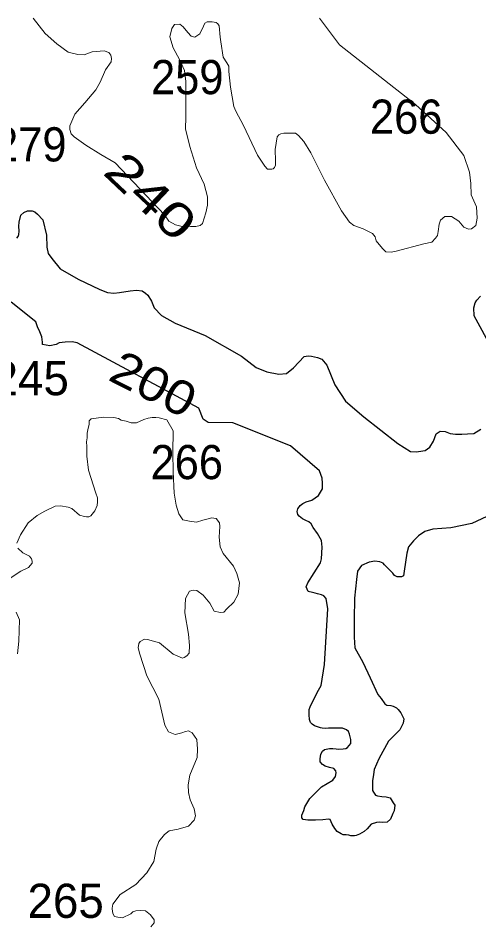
# Model space of a CAD drawing. Extents: x 445.4 to 500, y 8728.7 to 8784.
# Drawn here: x 479.664 to 481.821, y 8779.753 to 8784.001 of the extents above; entities that cross this region are included whole.
import ezdxf
from ezdxf.enums import TextEntityAlignment as Align

# ---------------------------------------------------------------- set-up
doc = ezdxf.new("R2010")
doc.units = 0
doc.header["$LTSCALE"] = 0.064
doc.layers.add('1', color=7, linetype='Continuous', lineweight=25)
doc.layers.add('2', color=7, linetype='Continuous', lineweight=13)
doc.layers.add('21', color=7, linetype='Continuous')
doc.layers.add('61', color=7, linetype='Continuous')

msp = doc.modelspace()

# ---------------------------------------------------------------- linework, layer by layer
at = {"layer": '1'}
for points in [[(479.6569, 8782.9699), (479.6644, 8782.9774), (479.6674, 8782.988), (479.6682, 8783.0038), (479.6674, 8783.0272), (479.6682, 8783.0453), (479.6759, 8783.0788), (479.6902, 8783.0902), (479.7068, 8783.0977), (479.7287, 8783.0977), (479.7415, 8783.0932), (479.7551, 8783.0834), (479.78, 8783.0562), (479.7966, 8782.9846), (479.7982, 8782.9283), (479.805, 8782.8989), (479.8216, 8782.8748), (479.8601, 8782.8265), (479.9446, 8782.779), (480.0459, 8782.7303), (480.0824, 8782.7162), (480.1118, 8782.712), (480.1385, 8782.7162), (480.1876, 8782.7232), (480.2171, 8782.726), (480.2438, 8782.7232), (480.2592, 8782.7134), (480.2704, 8782.7036), (480.2887, 8782.6756), (480.3013, 8782.6433), (480.3346, 8782.6087), (480.3992, 8782.5723), (480.5396, 8782.5148), (480.7094, 8782.4181), (480.7782, 8782.3648), (480.8273, 8782.3438), (480.8273, 8782.3438), (480.8849, 8782.3325), (480.8849, 8782.3325), (480.9199, 8782.3368), (480.9522, 8782.3634), (481.0028, 8782.4153), (481.021, 8782.4195), (481.0364, 8782.4167), (481.0659, 8782.4111), (481.085, 8782.4032), (481.1089, 8782.3752), (481.1468, 8782.2827), (481.1959, 8782.207)], [(481.8837, 8782.4485), (481.798, 8782.6069), (481.7977, 8782.6445), (481.8033, 8782.667), (481.8118, 8782.6796), (481.8286, 8782.6992)], [(481.0809, 8780.5527), (481.0892, 8780.5669), (481.0986, 8780.574), (481.1211, 8780.5787), (481.1364, 8780.5787), (481.1518, 8780.5775), (481.1647, 8780.5763), (481.1848, 8780.5775), (481.1978, 8780.5798), (481.2061, 8780.5846), (481.2061, 8780.5846), (481.2214, 8780.6023), (481.2214, 8780.6211), (481.2144, 8780.6469), (481.2097, 8780.6587), (481.2014, 8780.6669), (481.1826, 8780.6752), (481.1613, 8780.674), (481.1306, 8780.674), (481.1164, 8780.674), (481.1023, 8780.6728), (481.0869, 8780.6752), (481.0798, 8780.6764), (481.0656, 8780.6811), (481.0515, 8780.6858), (481.0408, 8780.6929), (481.0326, 8780.7011), (481.0279, 8780.7153), (481.0267, 8780.7365), (481.0267, 8780.7613), (481.0302, 8780.7743), (481.0633, 8780.8415), (481.0822, 8780.8745), (481.0987, 8780.9736), (481.1129, 8781.234), (481.1058, 8781.2823), (481.0952, 8781.2941), (481.0846, 8781.3), (481.0657, 8781.3047), (481.0539, 8781.3071), (481.0421, 8781.3106), (481.0208, 8781.3142), (481.0208, 8781.3142), (481.0125, 8781.3366), (481.0196, 8781.3553), (481.0799, 8781.4485), (481.0834, 8781.4685), (481.0869, 8781.5228), (481.0834, 8781.5534), (481.0645, 8781.5865), (481.0456, 8781.6148), (481.0362, 8781.6313), (481.0244, 8781.6419), (481.0102, 8781.6478), (480.9948, 8781.656), (480.9866, 8781.6619), (480.9795, 8781.6678), (480.9724, 8781.6761), (480.97, 8781.6891), (480.9724, 8781.702), (480.9842, 8781.7174), (480.9972, 8781.7268), (481.0125, 8781.7351), (481.0385, 8781.7422), (481.0705, 8781.7642), (481.0882, 8781.7961), (481.0882, 8781.822), (481.087, 8781.8456), (481.0743, 8781.8806), (480.939, 8781.9968), (480.6685, 8782.1044), (480.5529, 8782.107), (480.5299, 8782.122), (480.5099, 8782.1739), (479.9406, 8782.4806), (479.9173, 8782.4848), (479.8834, 8782.4827), (479.8559, 8782.4806), (479.841, 8782.4721), (479.841, 8782.4721), (479.8114, 8782.4658), (479.7775, 8782.4721), (479.7775, 8782.4827), (479.7754, 8782.5081), (479.7648, 8782.5314), (479.7542, 8782.5546), (479.7458, 8782.5779), (479.6314, 8782.6709)], [(481.1959, 8782.207), (481.2815, 8782.1326), (481.4415, 8782.0079), (481.5005, 8781.9714), (481.5286, 8781.97), (481.558, 8781.9742), (481.5693, 8781.9756), (481.5917, 8781.991), (481.6086, 8782.0191), (481.6208, 8782.0536), (481.6208, 8782.0536), (481.6391, 8782.0662), (481.6629, 8782.0648), (481.6868, 8782.055), (481.7107, 8782.0522), (481.7415, 8782.0522), (481.7668, 8782.0536), (481.7963, 8782.055), (481.83, 8782.076)], [(481.8576, 8781.6656), (481.7879, 8781.6337), (481.6887, 8781.6125)], [(481.6887, 8781.6125), (481.6049, 8781.6066), (481.5671, 8781.596), (481.5376, 8781.5759), (481.5139, 8781.5523), (481.4915, 8781.524), (481.4832, 8781.4945), (481.4703, 8781.4096), (481.4679, 8781.3884), (481.4584, 8781.3837), (481.4384, 8781.3837), (481.4254, 8781.3896), (481.4171, 8781.4014), (481.4006, 8781.4179), (481.3781, 8781.4403), (481.3722, 8781.4474), (481.3569, 8781.4533), (481.3336, 8781.4565), (481.3064, 8781.4529), (481.271, 8781.4364), (481.2521, 8781.4105), (481.2474, 8781.3704), (481.2391, 8781.2831), (481.237, 8781.1844), (481.237, 8781.1006), (481.2406, 8781.0511), (481.2772, 8780.9838), (481.3114, 8780.9107), (481.3472, 8780.8331), (481.3625, 8780.813), (481.3802, 8780.7883), (481.3897, 8780.7824), (481.4086, 8780.7812), (481.4192, 8780.7776), (481.4345, 8780.7694), (481.4428, 8780.7623), (481.4558, 8780.7458), (481.4688, 8780.7187), (481.4664, 8780.6986), (481.4511, 8780.6668), (481.3979, 8780.6137), (481.3528, 8780.5315), (481.3304, 8780.4808), (481.3269, 8780.4572), (481.3221, 8780.4277), (481.3221, 8780.4029), (481.3233, 8780.3829), (481.3269, 8780.3746), (481.3363, 8780.3605), (481.3457, 8780.3569), (481.3658, 8780.3546), (481.3859, 8780.3522), (481.4048, 8780.3475), (481.4201, 8780.3251), (481.4272, 8780.3145), (481.4237, 8780.2873), (481.4178, 8780.2755), (481.4072, 8780.2484), (481.3906, 8780.2343), (481.3906, 8780.2343), (481.3694, 8780.2331), (481.3564, 8780.2343), (481.341, 8780.2331), (481.3171, 8780.2252), (481.2971, 8780.2028), (481.2841, 8780.191), (481.2616, 8780.178), (481.2463, 8780.1721), (481.238, 8780.1709), (481.2215, 8780.1709), (481.212, 8780.1733), (481.199, 8780.1744), (481.1861, 8780.1756), (481.1766, 8780.1792), (481.1577, 8780.191), (481.1459, 8780.2051), (481.1341, 8780.2252), (481.1247, 8780.2464), (481.1164, 8780.2488), (481.0904, 8780.2452), (481.0562, 8780.2429), (481.0266, 8780.2429), (481.0207, 8780.244), (480.9983, 8780.2464), (480.9912, 8780.2547), (480.9912, 8780.2676), (481.0007, 8780.2889), (481.0054, 8780.3066), (481.0289, 8780.3451), (481.0833, 8780.3994), (481.1364, 8780.4312), (481.1494, 8780.4489), (481.1529, 8780.4654), (481.1506, 8780.4749), (481.1423, 8780.4855), (481.1211, 8780.4902), (481.101, 8780.4961), (481.088, 8780.5044), (481.0774, 8780.5162), (481.0774, 8780.5303), (481.0809, 8780.5527)]]:
    msp.add_lwpolyline(points, dxfattribs=at)
at = {"layer": '2'}
for points in [[(481.0745, 8784.0012), (481.1681, 8783.8757), (481.5247, 8783.597), (481.6681, 8783.4654), (481.7495, 8783.357), (481.7767, 8783.2796), (481.7832, 8783.2269), (481.785, 8783.1731), (481.8093, 8783.1176), (481.8128, 8783.0638), (481.8058, 8783.0291), (481.7867, 8783.0135), (481.7728, 8783.0118), (481.7502, 8783.0222), (481.7276, 8783.0499), (481.6929, 8783.0725), (481.6616, 8783.0725), (481.6407, 8783.0551), (481.6355, 8783.036), (481.6303, 8783.0013), (481.6268, 8782.9823), (481.6182, 8782.9701), (481.6008, 8782.951), (481.5626, 8782.9441), (481.434, 8782.9094), (481.4096, 8782.9042), (481.3853, 8782.9059), (481.3697, 8782.9215), (481.3401, 8782.958), (481.3349, 8782.9771), (481.3228, 8782.9927), (481.2793, 8783.0135), (481.2359, 8783.0291), (481.215, 8783.0447), (481.1768, 8783.0985), (481.0986, 8783.2425), (481.0339, 8783.3701), (481.0009, 8783.4239), (480.9766, 8783.4516), (480.9627, 8783.462), (480.9071, 8783.462), (480.8932, 8783.4586), (480.8845, 8783.4551), (480.8758, 8783.4447), (480.8671, 8783.3857), (480.8689, 8783.3319), (480.8689, 8783.3128), (480.8637, 8783.3007), (480.8584, 8783.2955), (480.8515, 8783.2937), (480.8306, 8783.2937), (480.8185, 8783.3076), (480.7837, 8783.3597), (480.7194, 8783.4985), (480.6823, 8783.5651), (480.6736, 8783.5877), (480.658, 8783.6779), (480.6493, 8783.7508), (480.6493, 8783.7768), (480.6406, 8783.7924), (480.6232, 8783.8189), (480.612, 8783.8909), (480.6094, 8783.9122), (480.6041, 8783.9645)], [(480.4213, 8783.973), (480.3958, 8783.9719), (480.3833, 8783.953), (480.374, 8783.9143), (480.3899, 8783.8619), (480.4194, 8783.808), (480.4427, 8783.7553), (480.4488, 8783.7039), (480.4488, 8783.6328), (480.4488, 8783.5365), (480.4476, 8783.4826), (480.4672, 8783.4005), (480.4991, 8783.3001), (480.5348, 8783.2233), (480.5495, 8783.1633), (480.5507, 8783.1253), (480.5421, 8783.0885), (480.5262, 8783.0383), (480.5151, 8783.0298), (480.4955, 8783.0249), (480.471, 8783.0249), (480.4256, 8783.0273), (480.3998, 8783.0334), (480.3692, 8783.0494), (480.3495, 8783.08), (480.1177, 8783.3237), (480.051, 8783.3625), (479.9799, 8783.4066), (479.9259, 8783.4446), (479.9124, 8783.4593), (479.905, 8783.4789), (479.9063, 8783.496), (479.9296, 8783.5512), (479.9762, 8783.6051), (480.0277, 8783.6651), (480.0485, 8783.7018), (480.0733, 8783.7589), (480.0991, 8783.7957), (480.1015, 8783.8128), (480.0978, 8783.8275), (480.088, 8783.8398), (480.0672, 8783.8484), (480.0107, 8783.8435), (479.9727, 8783.8288), (479.9433, 8783.8312), (479.8979, 8783.841), (479.8448, 8783.8804), (479.7909, 8783.9294), (479.7334, 8784.0004)], [(480.4213, 8783.973), (480.4362, 8783.9598), (480.4581, 8783.9335), (480.4735, 8783.9171), (480.4916, 8783.9127), (480.5148, 8783.928), (480.5308, 8783.9632), (480.5383, 8783.9775), (480.5494, 8783.9834), (480.572, 8783.9843), (480.5909, 8783.9815), (480.5993, 8783.9739), (480.6041, 8783.9645)], [(479.9904, 8782.0719), (479.9958, 8782.0986), (479.997, 8782.1145), (480.0056, 8782.1243), (480.0634, 8782.1311), (480.1122, 8782.1301), (480.1338, 8782.1254), (480.1457, 8782.117), (480.1688, 8782.1124), (480.1928, 8782.1044), (480.2185, 8782.1054), (480.2355, 8782.1131), (480.2524, 8782.1208), (480.2725, 8782.127), (480.2909, 8782.1301), (480.3079, 8782.1301), (480.3079, 8782.1301), (480.3244, 8782.1279), (480.3598, 8782.1187), (480.3896, 8782.0669), (480.388, 8781.9654), (480.3896, 8781.8761), (480.3942, 8781.776), (480.4034, 8781.7191), (480.4158, 8781.6791), (480.4343, 8781.6513), (480.4659, 8781.6443), (480.4982, 8781.6396), (480.5291, 8781.6489), (480.5537, 8781.655), (480.5691, 8781.6596), (480.5907, 8781.6566), (480.6061, 8781.6366), (480.6077, 8781.6196), (480.6046, 8781.5688), (480.6092, 8781.5242), (480.6231, 8781.4934), (480.6724, 8781.4334), (480.6878, 8781.3995), (480.7001, 8781.3555), (480.6939, 8781.3017), (480.6739, 8781.2647), (480.64, 8781.2339), (480.6261, 8781.2185), (480.6107, 8781.217), (480.5814, 8781.2232), (480.5614, 8781.2601), (480.5306, 8781.297), (480.4998, 8781.3201), (480.4828, 8781.3217), (480.4659, 8781.3171), (480.4474, 8781.2817), (480.4443, 8781.2155), (480.4612, 8781.1154), (480.4659, 8781.0615), (480.4643, 8781.0261), (480.4643, 8781.0261), (480.4535, 8781.0138), (480.4412, 8781.0061), (480.4335, 8781.003), (480.3888, 8781.0215), (480.3256, 8781.0739), (480.2693, 8781.0901), (480.2554, 8781.0916), (480.2354, 8781.0808), (480.2293, 8781.0716), (480.2262, 8781.0516), (480.2339, 8781.0208), (480.2662, 8780.9192), (480.3217, 8780.8099), (480.351, 8780.6883), (480.3669, 8780.6578), (480.3669, 8780.6578), (480.3993, 8780.6455), (480.4116, 8780.6486), (480.4301, 8780.6532), (480.4471, 8780.6594), (480.4471, 8780.6594), (480.4609, 8780.6624), (480.4779, 8780.6532), (480.4995, 8780.6209), (480.5041, 8780.5762), (480.5025, 8780.5378), (480.4671, 8780.4546), (480.4594, 8780.4085), (480.4609, 8780.3731), (480.4686, 8780.3392), (480.4871, 8780.2961), (480.4933, 8780.2638), (480.4871, 8780.2438), (480.4609, 8780.2161), (480.4126, 8780.2009), (480.371, 8780.1932), (480.3494, 8780.1763), (480.3217, 8780.144), (480.3093, 8780.107), (480.2985, 8780.0501), (480.2662, 8779.9962), (480.2153, 8779.9423), (480.1414, 8779.8946), (480.1075, 8779.85)], [(479.6578, 8781.5419), (479.6749, 8781.5798), (479.7104, 8781.636), (479.7532, 8781.6702), (479.7887, 8781.691), (479.8376, 8781.7142), (479.862, 8781.7166), (479.8975, 8781.7105), (479.9146, 8781.7032), (479.9513, 8781.6727), (479.9746, 8781.6666), (479.9831, 8781.6641), (479.9941, 8781.6653), (480.0039, 8781.669), (480.0235, 8781.6934), (480.0333, 8781.7179), (480.0357, 8781.735), (480.0345, 8781.7545), (480.0272, 8781.7753), (479.9933, 8781.8836), (479.986, 8781.9496), (479.9848, 8781.9728), (479.9854, 8781.976), (479.9854, 8781.9869), (479.9854, 8782.0007), (479.9845, 8782.0096), (479.984, 8782.0167), (479.9864, 8782.0343), (479.9872, 8782.0571), (479.9904, 8782.0719)], [(479.6271, 8781.3772), (479.676, 8781.4102), (479.7116, 8781.4271), (479.73, 8781.4479), (479.7287, 8781.4577), (479.7263, 8781.4687), (479.7165, 8781.4809), (479.6859, 8781.4955), (479.6627, 8781.5187)], [(479.6608, 8781.0232), (479.6674, 8781.0816), (479.6699, 8781.1817), (479.6552, 8781.2184)], [(480.1075, 8779.85), (480.1044, 8779.8315), (480.1059, 8779.8146), (480.109, 8779.8038), (480.1152, 8779.793), (480.1306, 8779.7884), (480.1521, 8779.7853), (480.1907, 8779.8053), (480.1999, 8779.8146), (480.2153, 8779.8192), (480.2354, 8779.8207), (480.26, 8779.8192), (480.2831, 8779.8007), (480.3001, 8779.7761), (480.3001, 8779.7622), (480.2847, 8779.7438)]]:
    msp.add_lwpolyline(points, dxfattribs=at)

# ---------------------------------------------------------------- texts
at = {"layer": '21', "width": 0.95}
for s, p in [('259', (480.2859, 8783.6448)), ('266', (481.3108, 8783.4596)), ('279', (479.5511, 8783.3299)), ('266', (480.2836, 8781.8412))]:
    msp.add_text(s, height=0.16, dxfattribs=at).set_placement(p)
at = {"layer": '21'}
for s, p in [('245', (479.5443, 8782.2344)), ('265', (479.7078, 8779.7858))]:
    msp.add_text(s, height=0.16, dxfattribs=at).set_placement(p)
at = {"layer": '61'}
for s, rotation, width, p in [('240', 316.609, 1.35, (480.2296, 8783.109)), ('200', 333.147, 1.15, (480.2616, 8782.2158))]:
    msp.add_text(s, height=0.16, rotation=rotation, dxfattribs=dict(at, width=width)).set_placement(p, align=Align.CENTER)

doc.saveas('drawing.dxf')
